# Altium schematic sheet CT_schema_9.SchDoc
size 382 x 278 mm
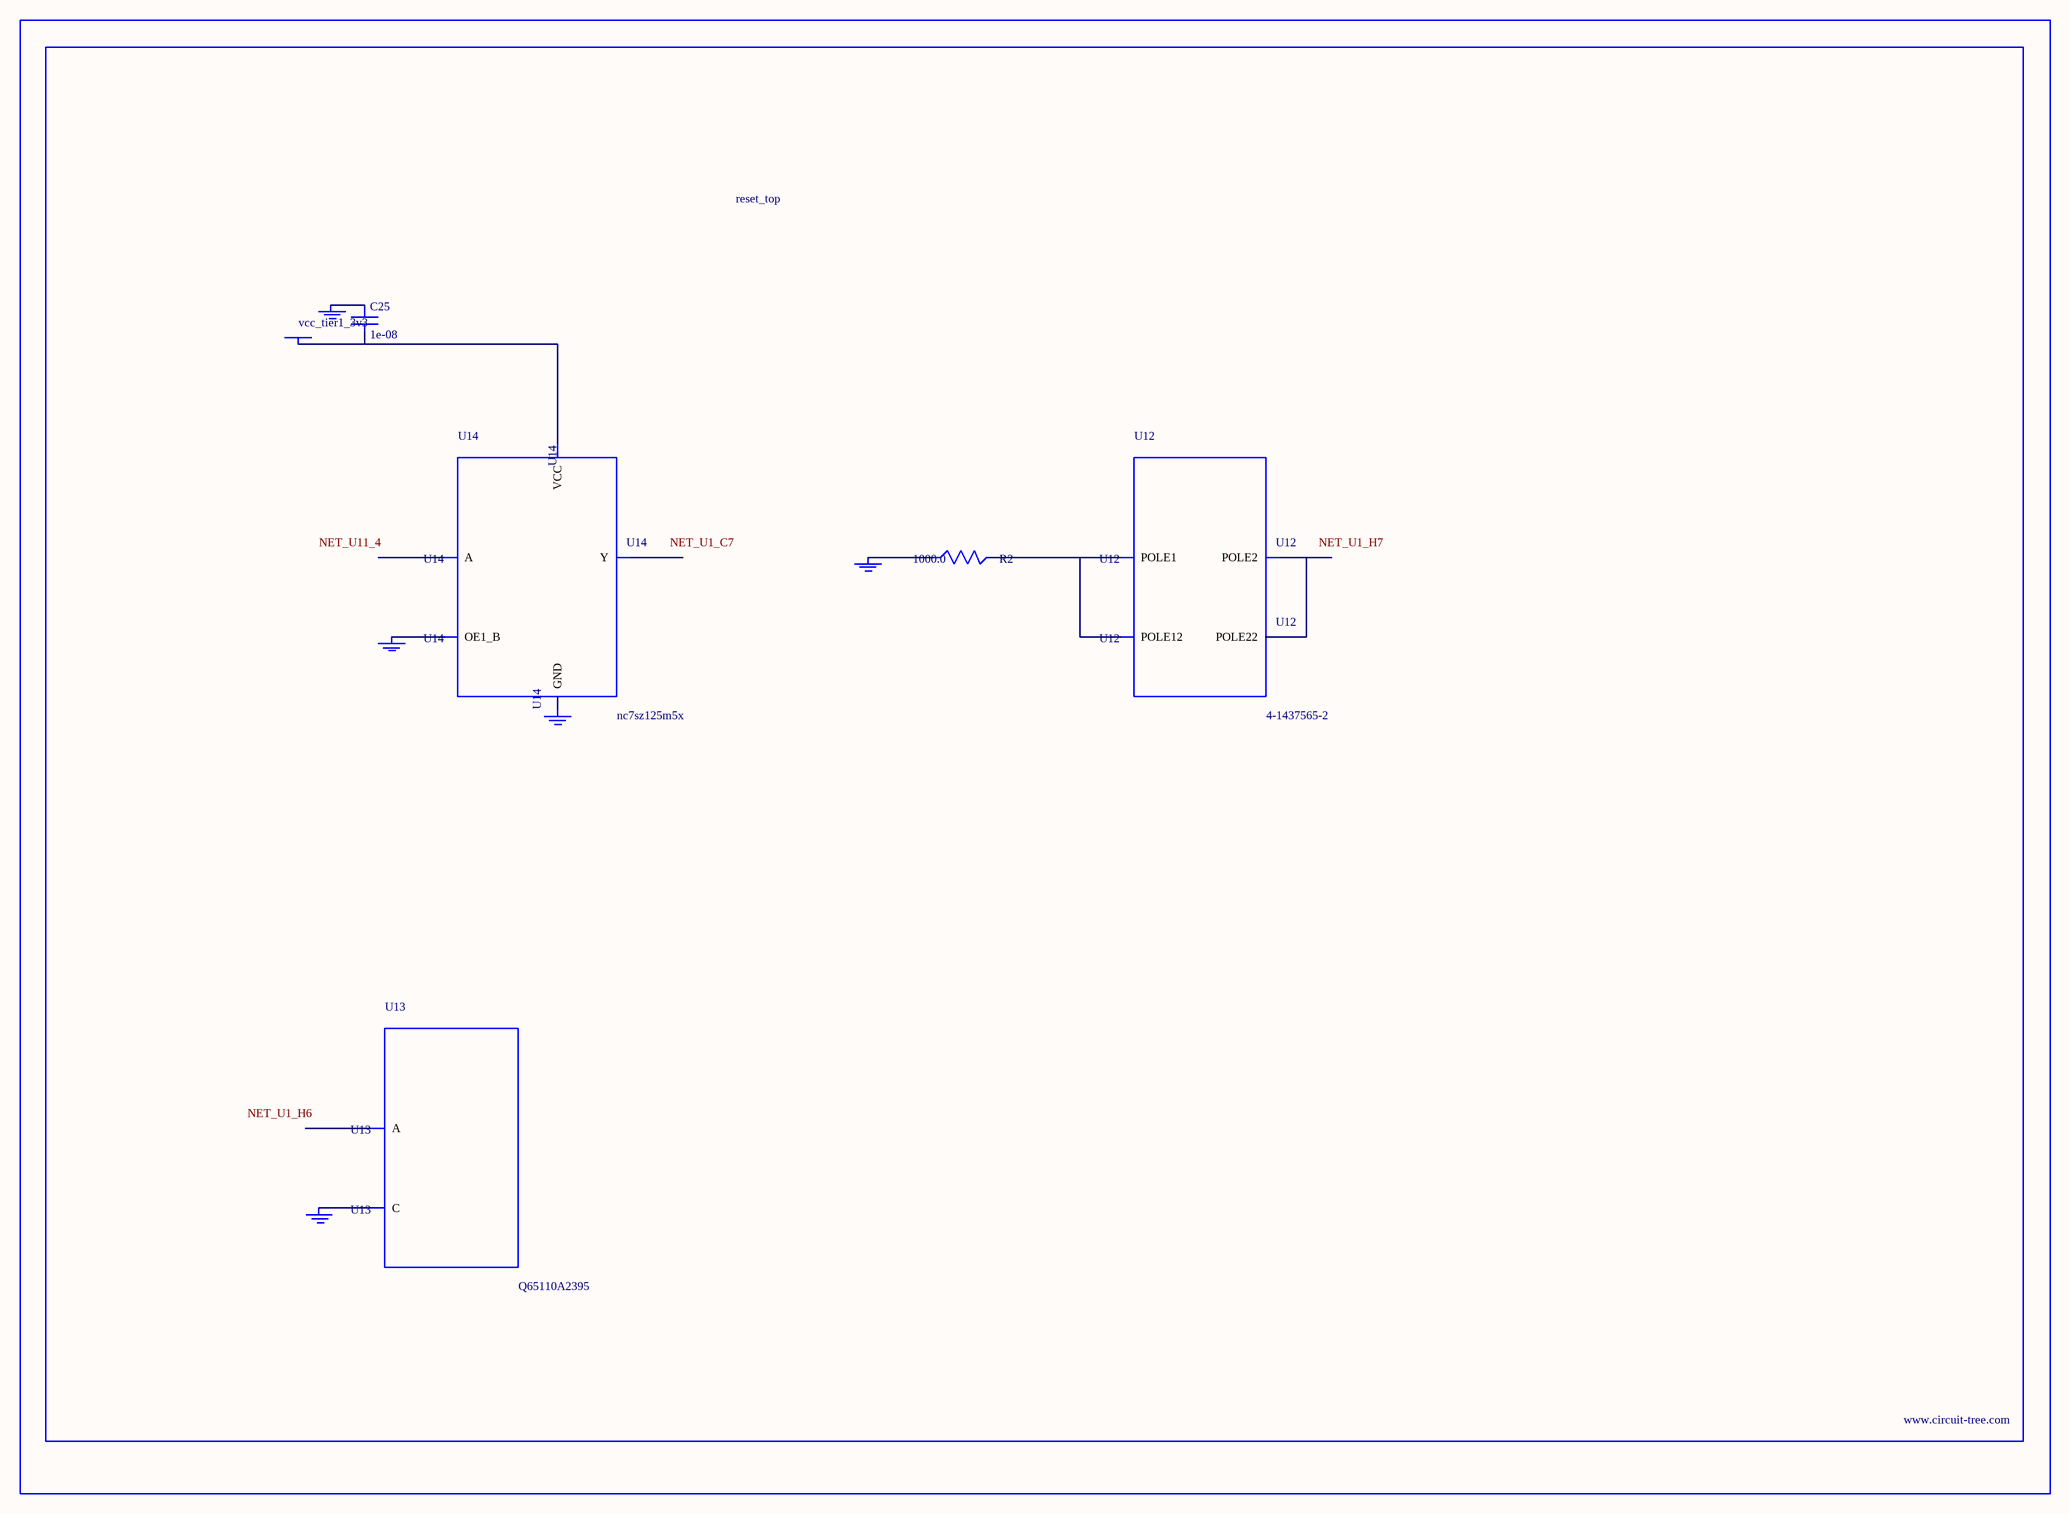
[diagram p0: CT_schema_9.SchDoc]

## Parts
BORDER8  (no value)
C25  1e-08  [C0402]
GND_INSTANCE_8_0  (no value)
GND_INSTANCE_8_1  (no value)
GND_INSTANCE_8_2  (no value)
GND_INSTANCE_8_3  (no value)
GND_INSTANCE_8_4  (no value)
POWER_INSTANCE_8_0  vcc_tier1_3v3
R2  1000.0  [R0603]
U12  4-1437565-2  [SW_4-1437565-2]
U13  Q65110A2395  [LGM67K-G1J2-24-Z]
U14  nc7sz125m5x  [NC7SZ125M5X]

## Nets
NetC25_1: C25.1 GND_INSTANCE_8_2.0(GND)
NetC25_2: C25.2 POWER_INSTANCE_8_0.0(PWR) U14.5(VCC)
NetGND_INSTANCE_8_0_0: GND_INSTANCE_8_0.0(GND) R2.1
NetGND_INSTANCE_8_1_0: GND_INSTANCE_8_1.0(GND) U13.C
NetGND_INSTANCE_8_3_0: GND_INSTANCE_8_3.0(GND) U14.1(OE1_B)
NetGND_INSTANCE_8_4_0: GND_INSTANCE_8_4.0(GND) U14.3(GND)
NetR2_2: R2.2 U12.1(POLE1) U12.2(POLE12)
NetU12_3: U12.3(POLE2) U12.4(POLE22)

Not connected (* = marked no-connect by the designer): U13 A; U14 2(A) 4(Y)

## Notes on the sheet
- Labels drawn without touching a wire or pin: NET_U1_C7, NET_U1_H6, NET_U1_H7, NET_U11_4

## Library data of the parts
BORDER8 = BORDER_PAGE8
C25 = C0402C103K3RAC
GND_INSTANCE_8_0-GND_INSTANCE_8_4 = GND
POWER_INSTANCE_8_0 = PWR
R2 = RC0603JR-071KL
